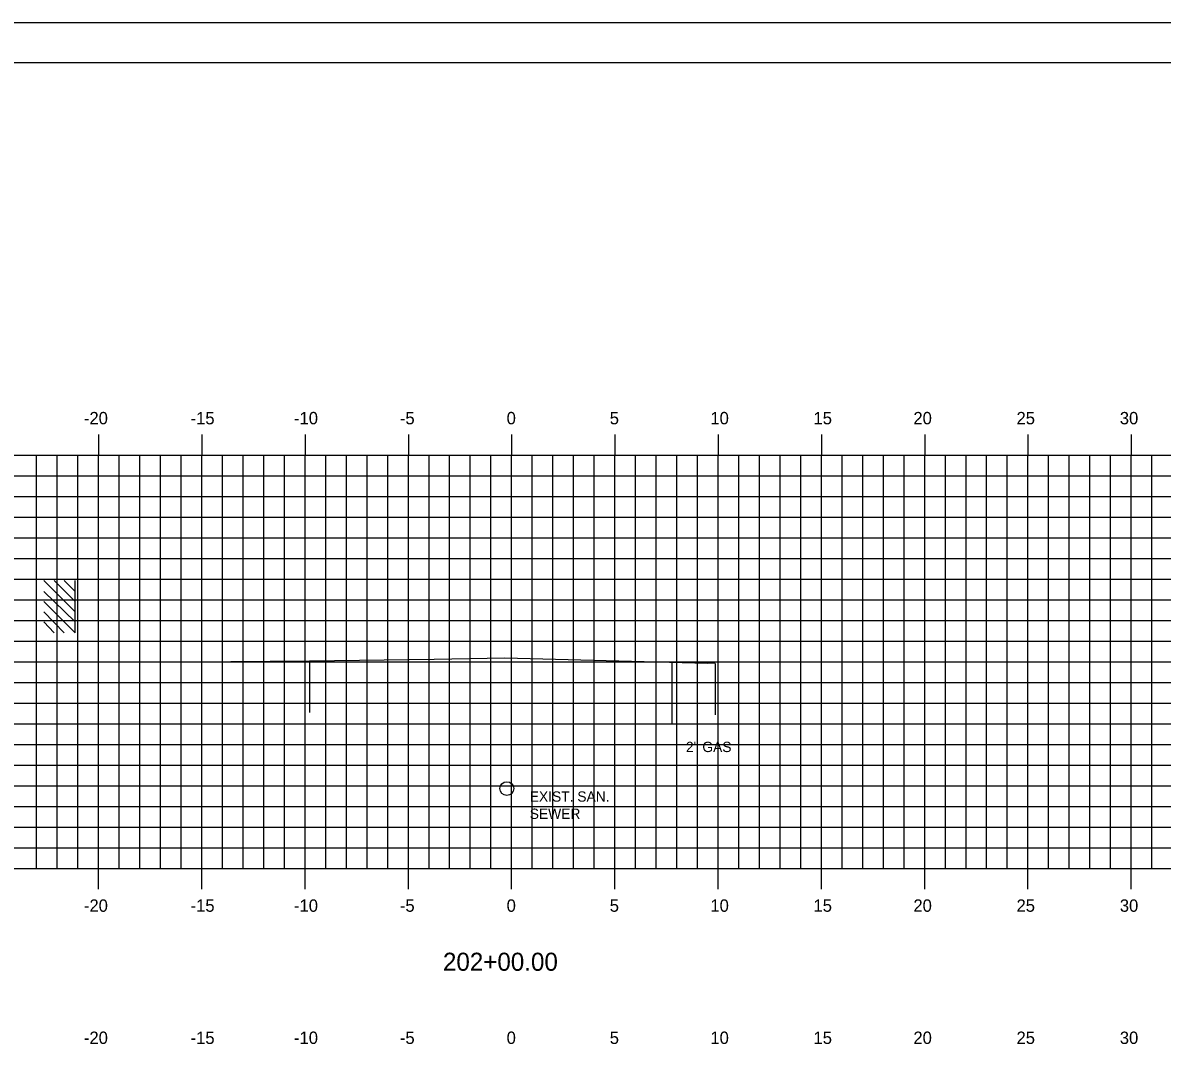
# Model space of a CAD drawing. Extents: x 1023905 to 1024075, y 394697 to 394807.
# Drawn here: x 1023964 to 1024019.2, y 394756.9 to 394806.5 of the extents above; entities that cross this region are included whole.
import ezdxf

# ---------------------------------------------------------------- set-up
doc = ezdxf.new("R2010")
doc.units = 0
for name, color, linetype in [('BORDER', 7, 'Continuous'), ('D_Text_Monospaced', 7, 'Continuous'), ('H_V ANNOTATION', 7, 'Continuous'), ('MAJOR', 7, 'Continuous'), ('MINOR', 7, 'Continuous'), ('PLOT BOUNDARY', 7, 'Continuous'), ('S_Buildings_SillElevation', 7, 'Continuous'), ('S_Roadway_Centerline', 7, 'Continuous'), ('S_Roadway_Edge_Pavement', 7, 'Continuous'), ('S_Utilities_UG_Gas_Line', 7, 'Continuous'), ('S_Utilities_UG_Sanitary_Sewer', 7, 'Continuous')]:
    doc.layers.add(name, color=color, linetype=linetype)

msp = doc.modelspace()

# ---------------------------------------------------------------- linework, layer by layer
at = {"layer": 'BORDER'}
msp.add_line((1024072.667, 394804.607), (1023912.667, 394804.607), dxfattribs=at)
at = {"layer": 'MAJOR'}
for p, q in [((1023967.667, 394786.609), (1023967.667, 394785.607)), ((1023972.667, 394786.609), (1023972.667, 394785.607)), ((1023977.667, 394786.609), (1023977.667, 394785.607)), ((1023982.667, 394786.609), (1023982.667, 394785.607)), ((1023987.667, 394786.609), (1023987.667, 394785.607)), ((1023992.667, 394786.609), (1023992.667, 394785.607)), ((1023997.667, 394786.609), (1023997.667, 394785.607)), ((1024002.667, 394786.609), (1024002.667, 394785.607)), ((1024007.667, 394786.609), (1024007.667, 394785.607)), ((1024012.667, 394786.609), (1024012.667, 394785.607)), ((1024017.667, 394786.609), (1024017.667, 394785.607)), ((1023917.667, 394785.607), (1024057.667, 394785.607)), ((1023967.667, 394765.607), (1023967.667, 394785.607)), ((1023972.667, 394765.607), (1023972.667, 394785.607)), ((1023977.667, 394765.607), (1023977.667, 394785.607)), ((1023982.667, 394765.607), (1023982.667, 394785.607)), ((1023987.667, 394765.607), (1023987.667, 394785.607)), ((1023992.667, 394765.607), (1023992.667, 394785.607)), ((1023997.667, 394765.607), (1023997.667, 394785.607)), ((1024002.667, 394765.607), (1024002.667, 394785.607)), ((1024007.667, 394765.607), (1024007.667, 394785.607)), ((1024012.667, 394765.607), (1024012.667, 394785.607)), ((1024017.667, 394765.607), (1024017.667, 394785.607)), ((1023917.667, 394780.607), (1024057.667, 394780.607)), ((1023917.667, 394775.607), (1024057.667, 394775.607)), ((1023917.667, 394770.607), (1024057.667, 394770.607)), ((1023917.667, 394765.607), (1024057.667, 394765.607)), ((1023967.667, 394764.605), (1023967.667, 394765.607)), ((1023972.667, 394764.605), (1023972.667, 394765.607)), ((1023977.667, 394764.605), (1023977.667, 394765.607)), ((1023982.667, 394764.605), (1023982.667, 394765.607)), ((1023987.667, 394764.605), (1023987.667, 394765.607)), ((1023992.667, 394764.605), (1023992.667, 394765.607)), ((1023997.667, 394764.605), (1023997.667, 394765.607)), ((1024002.667, 394764.605), (1024002.667, 394765.607)), ((1024007.667, 394764.605), (1024007.667, 394765.607)), ((1024012.667, 394764.605), (1024012.667, 394765.607)), ((1024017.667, 394764.605), (1024017.667, 394765.607))]:
    msp.add_line(p, q, dxfattribs=at)
at = {"layer": 'MINOR'}
for p, q in [((1023964.667, 394765.607), (1023964.667, 394785.607)), ((1023965.667, 394765.607), (1023965.667, 394785.607)), ((1023966.667, 394765.607), (1023966.667, 394785.607)), ((1023968.667, 394765.607), (1023968.667, 394785.607)), ((1023969.667, 394765.607), (1023969.667, 394785.607)), ((1023970.667, 394765.607), (1023970.667, 394785.607)), ((1023971.667, 394765.607), (1023971.667, 394785.607)), ((1023973.667, 394765.607), (1023973.667, 394785.607)), ((1023974.667, 394765.607), (1023974.667, 394785.607)), ((1023975.667, 394765.607), (1023975.667, 394785.607)), ((1023976.667, 394765.607), (1023976.667, 394785.607)), ((1023978.667, 394765.607), (1023978.667, 394785.607)), ((1023979.667, 394765.607), (1023979.667, 394785.607)), ((1023980.667, 394765.607), (1023980.667, 394785.607)), ((1023981.667, 394765.607), (1023981.667, 394785.607)), ((1023983.667, 394765.607), (1023983.667, 394785.607)), ((1023984.667, 394765.607), (1023984.667, 394785.607)), ((1023985.667, 394765.607), (1023985.667, 394785.607)), ((1023986.667, 394765.607), (1023986.667, 394785.607)), ((1023988.667, 394765.607), (1023988.667, 394785.607)), ((1023989.667, 394765.607), (1023989.667, 394785.607)), ((1023990.667, 394765.607), (1023990.667, 394785.607)), ((1023991.667, 394765.607), (1023991.667, 394785.607)), ((1023993.667, 394765.607), (1023993.667, 394785.607)), ((1023994.667, 394765.607), (1023994.667, 394785.607)), ((1023995.667, 394765.607), (1023995.667, 394785.607)), ((1023996.667, 394765.607), (1023996.667, 394785.607)), ((1023998.667, 394765.607), (1023998.667, 394785.607)), ((1023999.667, 394765.607), (1023999.667, 394785.607)), ((1024000.667, 394765.607), (1024000.667, 394785.607)), ((1024001.667, 394765.607), (1024001.667, 394785.607)), ((1024003.667, 394765.607), (1024003.667, 394785.607)), ((1024004.667, 394765.607), (1024004.667, 394785.607)), ((1024005.667, 394765.607), (1024005.667, 394785.607)), ((1024006.667, 394765.607), (1024006.667, 394785.607)), ((1024008.667, 394765.607), (1024008.667, 394785.607)), ((1024009.667, 394765.607), (1024009.667, 394785.607)), ((1024010.667, 394765.607), (1024010.667, 394785.607)), ((1024011.667, 394765.607), (1024011.667, 394785.607)), ((1024013.667, 394765.607), (1024013.667, 394785.607)), ((1024014.667, 394765.607), (1024014.667, 394785.607)), ((1024015.667, 394765.607), (1024015.667, 394785.607)), ((1024016.667, 394765.607), (1024016.667, 394785.607)), ((1024018.667, 394765.607), (1024018.667, 394785.607)), ((1023917.667, 394784.607), (1024057.667, 394784.607)), ((1023917.667, 394783.607), (1024057.667, 394783.607)), ((1023917.667, 394782.607), (1024057.667, 394782.607)), ((1023917.667, 394781.607), (1024057.667, 394781.607)), ((1023917.667, 394779.607), (1024057.667, 394779.607)), ((1023917.667, 394778.607), (1024057.667, 394778.607)), ((1023917.667, 394777.607), (1024057.667, 394777.607)), ((1023917.667, 394776.607), (1024057.667, 394776.607)), ((1023917.667, 394774.607), (1024057.667, 394774.607)), ((1023917.667, 394773.607), (1024057.667, 394773.607)), ((1023917.667, 394772.607), (1024057.667, 394772.607)), ((1023917.667, 394771.607), (1024057.667, 394771.607)), ((1023917.667, 394769.607), (1024057.667, 394769.607)), ((1023917.667, 394768.607), (1024057.667, 394768.607)), ((1023917.667, 394767.607), (1024057.667, 394767.607)), ((1023917.667, 394766.607), (1024057.667, 394766.607))]:
    msp.add_line(p, q, dxfattribs=at)
at = {"layer": 'PLOT BOUNDARY'}
msp.add_lwpolyline([(1023904.574, 394696.548), (1024074.574, 394696.548), (1024074.574, 394806.548), (1023904.574, 394806.548)], close=True, dxfattribs=at)
at = {"layer": 'S_Buildings_SillElevation'}
for p, q in [((1023966.528, 394778.032), (1023965.019, 394779.541)), ((1023966.528, 394778.524), (1023965.511, 394779.541)), ((1023966.528, 394779.016), (1023966.003, 394779.541)), ((1023966.528, 394777.015), (1023966.528, 394779.541)), ((1023966.528, 394777.54), (1023965.019, 394779.016)), ((1023966.528, 394777.015), (1023965.019, 394778.524)), ((1023966.003, 394777.015), (1023965.019, 394778.032)), ((1023965.511, 394777.015), (1023965.019, 394777.54))]:
    msp.add_line(p, q, dxfattribs=at)
at = {"layer": 'S_Roadway_Centerline'}
msp.add_lwpolyline([(1023972.173, 394775.613), (1023977.878, 394775.653), (1023983.909, 394775.736), (1023987.345, 394775.801), (1023997.143, 394775.546), (1023997.529, 394775.552)], dxfattribs=at)
at = {"layer": 'S_Roadway_Edge_Pavement'}
for p, q in [((1023977.878, 394775.653), (1023977.878, 394773.153)), ((1023997.529, 394775.535), (1023997.529, 394773.035))]:
    msp.add_line(p, q, dxfattribs=at)
at = {"layer": 'S_Utilities_UG_Gas_Line'}
msp.add_line((1023995.429, 394775.58), (1023995.429, 394772.58), dxfattribs=at)
at = {"layer": 'S_Utilities_UG_Sanitary_Sewer'}
msp.add_circle((1023987.436, 394769.47), 0.333, dxfattribs=at)

# ---------------------------------------------------------------- texts
at = {"layer": 'D_Text_Monospaced'}
for s, height, p in [('2" GAS', 0.5, (1023996.107, 394771.239)), ('EXIST. SAN.', 0.49998, (1023988.544, 394768.837)), ('SEWER', 0.5, (1023988.544, 394768.003))]:
    msp.add_text(s, height=height, dxfattribs=at).set_placement(p)
at = {"layer": 'H_V ANNOTATION'}
for s, height, p in [('-20', 0.6, (1023966.96, 394787.107)), ('-15', 0.6, (1023972.124, 394787.107)), ('-10', 0.6, (1023977.132, 394787.107)), ('-5', 0.6, (1023982.257, 394787.107)), ('0', 0.6, (1023987.426, 394787.107)), ('5', 0.6, (1023992.418, 394787.107)), ('10', 0.6, (1023997.292, 394787.107)), ('15', 0.6, (1024002.284, 394787.107)), ('20', 0.6, (1024007.121, 394787.107)), ('25', 0.6, (1024012.113, 394787.107)), ('30', 0.6, (1024017.115, 394787.107)), ('-20', 0.6, (1023966.96, 394763.507)), ('-15', 0.6, (1023972.124, 394763.507)), ('-10', 0.6, (1023977.132, 394763.507)), ('-5', 0.6, (1023982.257, 394763.507)), ('0', 0.6, (1023987.426, 394763.507)), ('5', 0.6, (1023992.418, 394763.507)), ('10', 0.6, (1023997.292, 394763.507)), ('15', 0.6, (1024002.284, 394763.507)), ('20', 0.6, (1024007.121, 394763.507)), ('25', 0.6, (1024012.113, 394763.507)), ('30', 0.6, (1024017.115, 394763.507)), ('202+00.00', 0.875, (1023984.342, 394760.65)), ('-20', 0.6, (1023966.96, 394757.107)), ('-15', 0.6, (1023972.124, 394757.107)), ('-10', 0.6, (1023977.132, 394757.107)), ('-5', 0.6, (1023982.257, 394757.107)), ('0', 0.6, (1023987.426, 394757.107)), ('5', 0.6, (1023992.418, 394757.107)), ('10', 0.6, (1023997.292, 394757.107)), ('15', 0.6, (1024002.284, 394757.107)), ('20', 0.6, (1024007.121, 394757.107)), ('25', 0.6, (1024012.113, 394757.107)), ('30', 0.6, (1024017.115, 394757.107))]:
    msp.add_text(s, height=height, dxfattribs=at).set_placement(p)
at = {"layer": 'S_Roadway_Centerline'}
for s, p in [('L', (1023987.337, 394775.794)), ('C', (1023987.34, 394775.801))]:
    msp.add_text(s, height=0.0146, dxfattribs=at).set_placement(p)

doc.saveas('drawing.dxf')
